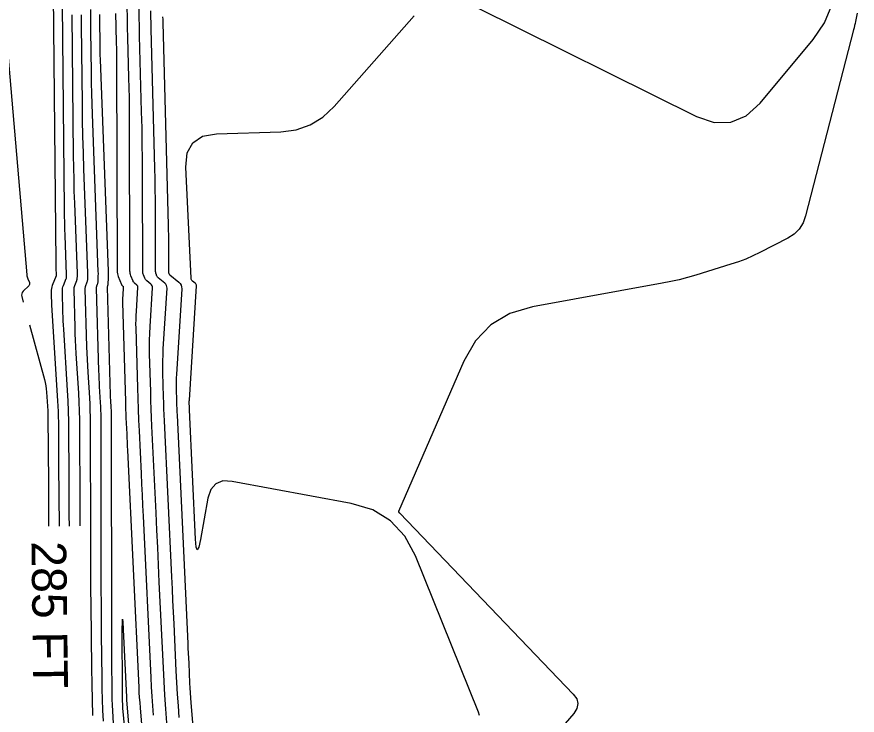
# Model space of a CAD drawing. Extents: x 1768942 to 1774819, y 723037 to 732099.
# Drawn here: x 1770861.8 to 1771007, y 724912 to 725032.8 of the extents above; entities that cross this region are included whole.
import ezdxf

# ---------------------------------------------------------------- set-up
doc = ezdxf.new("R2010")
doc.units = 0
doc.layers.add('R_Contour Annot', color=7, linetype='Continuous')
doc.layers.add('R_Contours', color=7, linetype='Continuous')

msp = doc.modelspace()

# ---------------------------------------------------------------- linework, layer by layer
at = {"layer": 'R_Contours'}
for points in [[(1770868.06, 725036.7), (1770868.51, 724990.24), (1770868.52, 724990.03), (1770868.52, 724989.81), (1770868.53, 724989.6), (1770868.53, 724989.38), (1770868.58, 724988.11), (1770868.58, 724988.1), (1770868.58, 724988.08), (1770868.58, 724988.07), (1770868.58, 724988.06), (1770868.58, 724988.02), (1770868.58, 724988.01), (1770868.58, 724988), (1770868.57, 724987.99), (1770868.57, 724987.98), (1770867.91, 724986.36), (1770867.82, 724986.1), (1770867.75, 724985.82), (1770867.72, 724985.54), (1770867.71, 724985.26), (1770867.74, 724984.11), (1770867.75, 724983.82), (1770867.76, 724983.53), (1770867.78, 724983.24), (1770867.79, 724982.96), (1770868.84, 724966.42), (1770868.89, 724965.49), (1770868.93, 724964.56), (1770868.95, 724963.62), (1770868.96, 724962.69), (1770868.97, 724958.95), (1770868.97, 724958.01), (1770868.98, 724957.08), (1770868.98, 724956.14), (1770868.99, 724955.21), (1770869.1, 724944.73)], [(1770870.87, 724944.75), (1770870.85, 724946.65), (1770870.83, 724948.45), (1770870.82, 724950.24), (1770870.81, 724952.04), (1770870.81, 724953.84), (1770870.8, 724961.02), (1770870.78, 724962.81), (1770870.74, 724964.61), (1770870.67, 724966.4), (1770870.57, 724968.19), (1770869.9, 724978.78), (1770869.85, 724979.49), (1770869.82, 724980.2), (1770869.79, 724980.91), (1770869.76, 724981.62), (1770869.66, 724985.41), (1770869.66, 724985.65), (1770869.69, 724985.88), (1770869.75, 724986.11), (1770869.83, 724986.33), (1770870.33, 724987.56), (1770870.35, 724987.61), (1770870.36, 724987.67), (1770870.37, 724987.72), (1770870.38, 724987.78), (1770870.39, 724988.02), (1770870.39, 724988.07), (1770870.39, 724988.13), (1770870.39, 724988.19), (1770870.39, 724988.25), (1770870.13, 724994.97), (1770870.1, 724996.11), (1770870.06, 724997.25), (1770870.04, 724998.39), (1770870.03, 724999.53), (1770869.68, 725034.91)], [(1770874.51, 725034.06), (1770874.52, 725032.24), (1770874.54, 725030.43), (1770874.61, 725023.18), (1770874.63, 725021.36), (1770874.67, 725019.55), (1770874.72, 725017.74), (1770874.78, 725015.93), (1770875.81, 724988.68), (1770875.82, 724988.48), (1770875.82, 724988.28), (1770875.81, 724988.08), (1770875.81, 724987.88), (1770875.76, 724986.84), (1770875.75, 724986.76), (1770875.74, 724986.68), (1770875.72, 724986.6), (1770875.69, 724986.52), (1770875.56, 724986.21), (1770875.53, 724986.13), (1770875.51, 724986.05), (1770875.5, 724985.97), (1770875.5, 724985.89), (1770875.91, 724971.57), (1770875.93, 724970.89), (1770875.96, 724970.21), (1770875.99, 724969.53), (1770876.03, 724968.85), (1770876.2, 724966.12), (1770876.24, 724965.44), (1770876.27, 724964.76), (1770876.29, 724964.08), (1770876.29, 724963.4), (1770876.33, 724933.49), (1770876.34, 724931.62), (1770876.35, 724929.74), (1770876.36, 724927.87), (1770876.38, 724926), (1770876.46, 724918.51), (1770876.49, 724916.63), (1770876.54, 724914.76), (1770876.61, 724912.89), (1770876.7, 724911.02)], [(1770885.41, 724912.05), (1770885.28, 724913.67), (1770885.17, 724915.3), (1770885.07, 724916.93), (1770884.98, 724918.56), (1770883.66, 724946.46), (1770883.58, 724948.3), (1770883.49, 724950.15), (1770883.4, 724952), (1770883.32, 724953.84), (1770882.97, 724961.23), (1770882.88, 724963.08), (1770882.81, 724964.93), (1770882.75, 724966.77), (1770882.69, 724968.62), (1770882.4, 724978.96), (1770882.38, 724979.69), (1770882.39, 724980.42), (1770882.41, 724981.15), (1770882.45, 724981.88), (1770882.7, 724986.01), (1770882.7, 724986.13), (1770882.67, 724986.23), (1770882.61, 724986.33), (1770882.53, 724986.41), (1770882.15, 724986.72), (1770882.06, 724986.8), (1770881.98, 724986.89), (1770881.92, 724986.99), (1770881.87, 724987.1), (1770881.49, 724988.03), (1770881.42, 724988.22), (1770881.37, 724988.42), (1770881.35, 724988.62), (1770881.34, 724988.83), (1770881.27, 725015.28), (1770881.26, 725017.02), (1770881.24, 725018.76), (1770881.21, 725020.49), (1770881.16, 725022.23), (1770880.98, 725029.18), (1770880.94, 725030.92), (1770880.9, 725032.66), (1770880.88, 725034.39)], [(1770887.73, 724910.75), (1770887.55, 724913.12), (1770887.38, 724915.5), (1770887.24, 724917.87), (1770887.11, 724920.25), (1770886.41, 724935.03), (1770886.27, 724938.02), (1770886.13, 724941.02), (1770885.99, 724944.01), (1770885.85, 724947.01), (1770885.14, 724962), (1770885.07, 724963.49), (1770885.01, 724964.98), (1770884.96, 724966.46), (1770884.92, 724967.95), (1770884.73, 724974.5), (1770884.71, 724975.69), (1770884.72, 724976.87), (1770884.75, 724978.05), (1770884.81, 724979.24), (1770885.23, 724985.93), (1770885.22, 724986.12), (1770885.17, 724986.29), (1770885.08, 724986.44), (1770884.94, 724986.58), (1770884.26, 724987.13), (1770884.14, 724987.23), (1770884.05, 724987.35), (1770883.97, 724987.47), (1770883.9, 724987.61), (1770883.67, 724988.18), (1770883.62, 724988.32), (1770883.59, 724988.47), (1770883.57, 724988.62), (1770883.56, 724988.77), (1770883.51, 725005.41), (1770883.5, 725008.14), (1770883.47, 725010.87), (1770883.42, 725013.6), (1770883.36, 725016.33), (1770883.01, 725029.5), (1770882.97, 725031.1), (1770882.94, 725032.7), (1770882.91, 725034.3)], [(1770889.87, 724911.65), (1770889.71, 724913.67), (1770889.57, 724915.69), (1770889.45, 724917.72), (1770889.34, 724919.74), (1770888.96, 724927.84), (1770888.87, 724929.86), (1770888.77, 724931.89), (1770888.68, 724933.91), (1770888.58, 724935.94), (1770887.31, 724962.95), (1770887.26, 724963.99), (1770887.22, 724965.02), (1770887.18, 724966.06), (1770887.15, 724967.1), (1770887.03, 724971.25), (1770887.02, 724972.28), (1770887.02, 724973.32), (1770887.05, 724974.35), (1770887.1, 724975.39), (1770887.75, 724985.85), (1770887.74, 724986.11), (1770887.67, 724986.35), (1770887.54, 724986.56), (1770887.36, 724986.74), (1770886.23, 724987.65), (1770886.16, 724987.72), (1770886.1, 724987.79), (1770886.05, 724987.87), (1770886, 724987.96), (1770885.86, 724988.33), (1770885.82, 724988.42), (1770885.8, 724988.51), (1770885.79, 724988.61), (1770885.78, 724988.71), (1770885.75, 724999.36), (1770885.74, 725001.17), (1770885.72, 725002.98), (1770885.69, 725004.79), (1770885.65, 725006.6), (1770885.01, 725030.64), (1770884.99, 725031.69), (1770884.97, 725032.75), (1770884.95, 725033.8)], [(1770941.19, 725034.46), (1770979.25, 725015.56), (1770982.34, 725014.51), (1770985.21, 725014.55), (1770987.84, 725015.67), (1770990.25, 725017.87), (1770999.43, 725028.87), (1771001.39, 725031.72), (1771002.68, 725034.77)], [(1770871.3, 725033.12), (1770871.54, 725008.81), (1770871.57, 725006.74), (1770871.61, 725004.68), (1770871.66, 725002.62), (1770871.74, 725000.56), (1770872.2, 724988.39), (1770872.2, 724988.29), (1770872.2, 724988.18), (1770872.2, 724988.08), (1770872.19, 724987.97), (1770872.17, 724987.55), (1770872.16, 724987.44), (1770872.15, 724987.34), (1770872.12, 724987.24), (1770872.08, 724987.14), (1770871.74, 724986.29), (1770871.68, 724986.11), (1770871.63, 724985.94), (1770871.61, 724985.75), (1770871.61, 724985.57), (1770871.79, 724979.14), (1770871.82, 724978), (1770871.87, 724976.87), (1770871.93, 724975.74), (1770872, 724974.6), (1770872.43, 724967.71), (1770872.52, 724966.19), (1770872.58, 724964.66), (1770872.62, 724963.13), (1770872.63, 724961.6), (1770872.65, 724948.72), (1770872.65, 724946.07), (1770872.66, 724944.77)], [(1770872.91, 725033.11), (1770872.92, 725031.33), (1770873.05, 725017.81), (1770873.09, 725014.96), (1770873.15, 725012.12), (1770873.23, 725009.27), (1770873.33, 725006.42), (1770874, 724988.54), (1770874.01, 724988.38), (1770874.01, 724988.23), (1770874.01, 724988.08), (1770874, 724987.92), (1770873.97, 724987.28), (1770873.96, 724987.14), (1770873.93, 724987.01), (1770873.9, 724986.88), (1770873.85, 724986.75), (1770873.65, 724986.25), (1770873.6, 724986.12), (1770873.57, 724985.99), (1770873.56, 724985.86), (1770873.55, 724985.73), (1770873.84, 724975.75), (1770873.87, 724974.64), (1770873.92, 724973.54), (1770873.97, 724972.44), (1770874.04, 724971.33), (1770874.32, 724966.92), (1770874.38, 724965.81), (1770874.42, 724964.71), (1770874.45, 724963.61), (1770874.46, 724962.5), (1770874.49, 724942.05), (1770874.5, 724939.31), (1770874.51, 724936.58), (1770874.53, 724933.84), (1770874.56, 724931.11), (1770874.68, 724920.18), (1770874.72, 724917.44), (1770874.79, 724914.71), (1770874.89, 724911.98)], [(1770878.6, 724908.47), (1770878.38, 724912.79), (1770878.33, 724913.8), (1770878.29, 724914.81), (1770878.26, 724915.82), (1770878.25, 724916.83), (1770878.2, 724920.89), (1770878.19, 724921.9), (1770878.19, 724922.91), (1770878.18, 724923.92), (1770878.18, 724924.94), (1770878.12, 724964.3), (1770878.12, 724964.56), (1770878.12, 724964.82), (1770878.1, 724965.07), (1770878.09, 724965.33), (1770878.03, 724966.36), (1770878.01, 724966.62), (1770878, 724966.88), (1770877.99, 724967.14), (1770877.98, 724967.39), (1770877.45, 724986.04), (1770877.45, 724986.08), (1770877.45, 724986.11), (1770877.46, 724986.14), (1770877.47, 724986.17), (1770877.52, 724986.28), (1770877.53, 724986.31), (1770877.54, 724986.34), (1770877.54, 724986.38), (1770877.55, 724986.41), (1770877.61, 724987.83), (1770877.62, 724988.08), (1770877.63, 724988.33), (1770877.62, 724988.58), (1770877.62, 724988.82), (1770876.23, 725025.43), (1770876.2, 725026.21), (1770876.18, 725026.98), (1770876.17, 725027.76), (1770876.16, 725028.54), (1770876.13, 725031.66), (1770876.12, 725032.43), (1770876.12, 725033.21)], [(1770878.85, 725033.36), (1770878.86, 725032.61), (1770878.88, 725031.87), (1770878.89, 725031.12), (1770878.97, 725028.14), (1770878.99, 725027.39), (1770879, 725026.64), (1770879.01, 725025.9), (1770879.02, 725025.15), (1770879.11, 724988.89), (1770879.13, 724988.63), (1770879.16, 724988.37), (1770879.22, 724988.12), (1770879.31, 724987.88), (1770879.86, 724986.5), (1770879.88, 724986.46), (1770879.9, 724986.42), (1770879.93, 724986.39), (1770879.97, 724986.36), (1770880.11, 724986.24), (1770880.14, 724986.21), (1770880.16, 724986.18), (1770880.18, 724986.14), (1770880.18, 724986.09), (1770880.08, 724984.53), (1770880.07, 724984.25), (1770880.06, 724983.97), (1770880.06, 724983.7), (1770880.06, 724983.42), (1770880.55, 724966.28), (1770880.57, 724965.58), (1770880.59, 724964.88), (1770880.62, 724964.18), (1770880.65, 724963.48), (1770880.78, 724960.68), (1770880.82, 724959.98), (1770880.85, 724959.28), (1770880.88, 724958.58), (1770880.92, 724957.88), (1770882.85, 724916.86), (1770882.9, 724915.98), (1770882.95, 724915.1), (1770883.02, 724914.22), (1770883.08, 724913.34), (1770886.81, 724868.55)], [(1770886.99, 725032.79), (1770887, 725032.29), (1770887.02, 725031.78), (1770887.94, 724996.73), (1770887.96, 724995.91), (1770887.98, 724995.1), (1770887.99, 724994.28), (1770887.99, 724993.46), (1770888.01, 724988.65), (1770888.01, 724988.61), (1770888.01, 724988.56), (1770888.02, 724988.52), (1770888.04, 724988.48), (1770888.11, 724988.31), (1770888.12, 724988.27), (1770888.15, 724988.23), (1770888.18, 724988.2), (1770888.21, 724988.17), (1770889.78, 724986.91), (1770890.01, 724986.68), (1770890.17, 724986.41), (1770890.26, 724986.11), (1770890.28, 724985.77), (1770889.36, 724970.94), (1770889.33, 724970.35), (1770889.31, 724969.77), (1770889.31, 724969.18), (1770889.32, 724968.59), (1770889.38, 724966.25), (1770889.4, 724965.66), (1770889.42, 724965.07), (1770889.45, 724964.49), (1770889.47, 724963.9), (1770891.33, 724924.47), (1770891.37, 724923.61), (1770891.41, 724922.76), (1770891.45, 724921.9), (1770891.49, 724921.04), (1770891.65, 724917.61), (1770891.7, 724916.75), (1770891.75, 724915.89), (1770891.81, 724915.03), (1770891.88, 724914.18), (1770894.75, 724879.73)], [(1770941.76, 724911.97), (1770941.61, 724912.6), (1770930.7, 724939.59), (1770928.86, 724943.01), (1770926.39, 724945.66), (1770923.3, 724947.54), (1770919.59, 724948.67), (1770899.02, 724952.47), (1770897.41, 724952.54), (1770896.18, 724952.07), (1770895.31, 724951.08), (1770894.8, 724949.56), (1770893.51, 724942.42), (1770893.22, 724941.09), (1770892.98, 724940.65), (1770892.81, 724941.12), (1770892.69, 724942.48), (1770891.64, 724964.85), (1770891.63, 724964.99), (1770891.63, 724965.12), (1770891.62, 724965.26), (1770891.62, 724965.4), (1770891.6, 724965.94), (1770891.6, 724966.08), (1770891.6, 724966.22), (1770891.6, 724966.35), (1770891.61, 724966.49), (1770892.84, 724986.25), (1770892.83, 724986.39), (1770892.79, 724986.52), (1770892.72, 724986.63), (1770892.62, 724986.73), (1770892.16, 724987.11), (1770892.06, 724987.21), (1770891.98, 724987.32), (1770891.93, 724987.45), (1770891.91, 724987.59), (1770891, 725006.81), (1770891.24, 725009.25), (1770892.19, 725011.02), (1770893.88, 725012.12), (1770896.3, 725012.55), (1770907.41, 725012.92), (1770910.07, 725013.26), (1770912.49, 725014.1), (1770914.68, 725015.44), (1770916.63, 725017.28), (1770930.45, 725032.97)], [(1771007.04, 725033.44), (1771006.75, 725031.98), (1771006.68, 725031.62), (1771006.6, 725031.26), (1771006.51, 725030.89), (1771006.42, 725030.53), (1770998.13, 724998.37), (1770997.68, 724997.15), (1770997.02, 724996.09), (1770996.14, 724995.22), (1770995.04, 724994.51), (1770990.22, 724992.04), (1770989, 724991.45), (1770987.77, 724990.91), (1770986.51, 724990.43), (1770985.22, 724990), (1770979.17, 724988.13), (1770977.73, 724987.71), (1770976.27, 724987.33), (1770974.81, 724987), (1770973.33, 724986.71), (1770950.93, 724982.65), (1770947.02, 724981.49), (1770943.73, 724979.53), (1770941.07, 724976.78), (1770939.05, 724973.24), (1770927.76, 724947.29), (1770927.75, 724947.26), (1770927.75, 724947.23), (1770927.76, 724947.21), (1770927.78, 724947.18), (1770927.89, 724947.06), (1770927.94, 724947.02), (1770927.96, 724946.99), (1770957.97, 724915.7), (1770958.56, 724914.88), (1770958.77, 724914.06), (1770958.6, 724913.22), (1770958.06, 724912.37), (1770954.64, 724908.4)], [(1770860.12, 725027.76), (1770863.5, 724988.2), (1770863.53, 724988.02), (1770863.56, 724987.85), (1770863.61, 724987.68), (1770863.67, 724987.51), (1770863.95, 724986.84), (1770864, 724986.68), (1770863.99, 724986.53), (1770863.94, 724986.39), (1770863.83, 724986.26), (1770862.89, 724985.34), (1770862.72, 724985.14), (1770862.63, 724984.91), (1770862.6, 724984.67), (1770862.64, 724984.41), (1770862.9, 724983.45)], [(1770863.97, 724979.54), (1770866.55, 724970.1), (1770866.68, 724969.55), (1770866.79, 724969), (1770866.86, 724968.44), (1770866.91, 724967.88), (1770867.12, 724964.65), (1770867.12, 724964.58), (1770867.13, 724964.5), (1770867.13, 724964.43), (1770867.13, 724964.36), (1770867.13, 724964.06), (1770867.13, 724963.99), (1770867.13, 724963.91), (1770867.13, 724963.84), (1770867.13, 724963.76), (1770867.26, 724952.09), (1770867.27, 724950.12), (1770867.28, 724948.15), (1770867.28, 724946.18), (1770867.27, 724944.71)], [(1770884.36, 724869.12), (1770880.13, 724913.27), (1770880.12, 724913.43), (1770880.11, 724913.59), (1770880.1, 724913.75), (1770880.09, 724913.91), (1770880.05, 724914.55), (1770880.05, 724914.71), (1770880.04, 724914.86), (1770880.04, 724915.01), (1770880.03, 724915.16), (1770880.03, 724915.77), (1770880.03, 724915.92), (1770880.02, 724916.08), (1770880.02, 724916.23), (1770880.02, 724916.38), (1770880.01, 724926.86), (1770880.02, 724928.21), (1770880.05, 724928.66), (1770880.1, 724928.21), (1770880.17, 724926.86), (1770880.73, 724915.17), (1770880.73, 724915.04), (1770880.74, 724914.9), (1770880.75, 724914.77), (1770880.76, 724914.64), (1770884.86, 724865.38)]]:
    msp.add_lwpolyline(points, dxfattribs=at)

# ---------------------------------------------------------------- texts
at = {"layer": 'R_Contour Annot'}
msp.add_text('285 FT', height=6, rotation=270.735, dxfattribs=at).set_placement((1770864.31, 724942.09))

doc.saveas('drawing.dxf')
